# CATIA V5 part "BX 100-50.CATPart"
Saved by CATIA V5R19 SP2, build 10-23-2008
Part number: BX 100-50
Bounding box of the stored display mesh (mm): x -18.951 to 18.951, y -18.952 to 18.952, z 0 to 230
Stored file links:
  C:\Users\Bora\Desktop\3D Katı model\BX serisi\BX 100\BX 100-50.CATPart
  C:\Program Files\Dassault Systemes\B19\intel_a\reffiles\standard\MetricThickPitch.txt
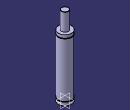
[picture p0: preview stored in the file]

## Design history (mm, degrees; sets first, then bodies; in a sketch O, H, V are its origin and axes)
Body1 (main body)
  Sketch1 on yz-plane, origin (0, 0, 0), H (0, 1, 0), V (0, 0, 1)
    point P1 (19, 170.5)
    line L1 (19, 179) -> (19, 170.5)
    point P4 (10, 229)
    line L2 (10, 229) -> (10, 179)
    point P6 (10, 229)
    arc A1 centre (9, 229) radius 1 from (10, 229) to (9, 230) ccw
    point P7 (19, 168.5)
    point P8 (19, 170.5)
    arc A2 centre (19, 169.5) radius 1 from (19, 170.5) to (19, 168.5) ccw
    point P9 (19, 11.5)
    point P10 (19, 168.5)
    line L3 (19, 168.5) -> (19, 11.5)
    point P11 (19, 9.5)
    point P12 (19, 11.5)
    arc A3 centre (19, 10.5) radius 1 from (19, 11.5) to (19, 9.5) ccw
    point P14 (19, 9.5)
    line L4 (19, 9.5) -> (19, 0)
    line L5 (19, 0) -> (0, 0)
    line L6 (19, 179) -> (10, 179)
    line L7 (9, 230) -> (0, 230)
    horizontal: L5 H, L6 H
    tangency: L7 A1
    coincidence: P1 P8, P4 P6, P7 P10, P9 P12, P11 P14
  Shaft1: profile Sketch1, axis Sketch1.V, angle 360
  Sketch2 on face of Shaft1 from Sketch1.L5, origin (0, 0, 0), H (1, 0, 0), V (0, -1, 0)
    point P1 (9, 0)
    distance P1 V = 9
  Hole1: placed by Sketch2, at (9, 0, 0) direction (0, 0, 1), diameter 4.917, depth 6, threaded "M6", thread diameter 6, thread depth 6, pitch 1
  Sketch3 on face of Shaft1 from Sketch1.L5, origin (0, 0, 0), H (1, 0, 0), V (0, -1, 0)
    point P1 (-9, 0)
    distance P1 V = 9
  Hole2: placed by Sketch3, at (-9, 0, 0) direction (0, 0, 1), diameter 4.917, depth 6, threaded "M6", thread diameter 6, thread depth 6, pitch 1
